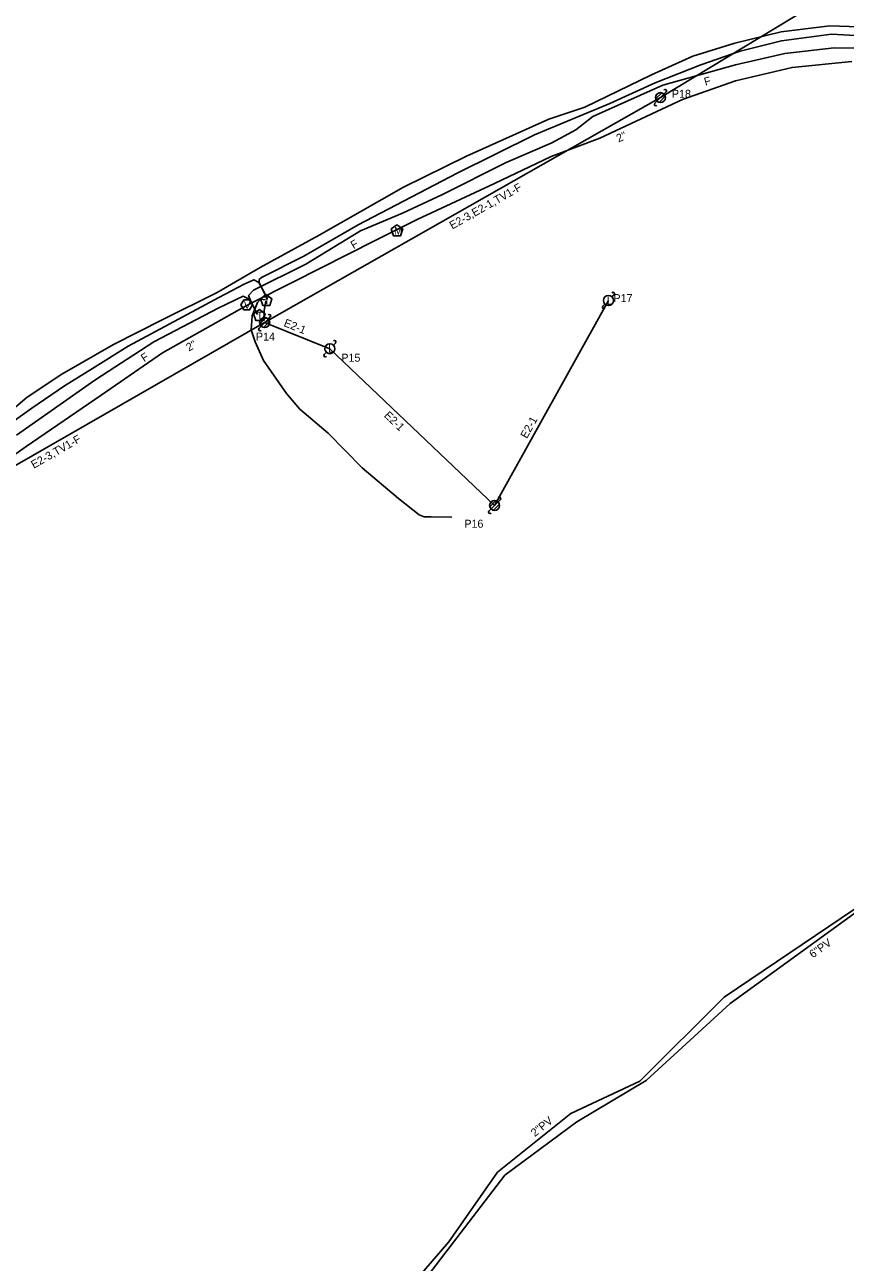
# Model space of a CAD drawing. Extents: x 1741604 to 1825760, y 1164229 to 1194908.
# Drawn here: x 1754935 to 1755344, y 1168344 to 1168963 of the extents above; entities that cross this region are included whole.
import ezdxf

# ---------------------------------------------------------------- set-up
doc = ezdxf.new("R2010")
doc.units = 0
for name, color, linetype in [('RD_EX_SU_H2O', 7, 'Continuous'), ('RD_EX_SU_Ovhd', 7, 'Continuous'), ('RD_EX_SU_Pole', 7, 'Continuous'), ('RD_EX_SU_Sewer', 7, 'Continuous'), ('RD_EX_SU_Telecom', 7, 'Continuous'), ('RD_EX_SU_TX_H2O', 7, 'Continuous'), ('RD_EX_SU_TX_Pole', 7, 'Continuous'), ('RD_EX_SU_TX_Sewer', 7, 'Continuous'), ('RD_EX_SU_TX_Telecom', 7, 'Continuous')]:
    doc.layers.add(name, color=color, linetype=linetype)

msp = doc.modelspace()

# ---------------------------------------------------------------- linework, layer by layer
at = {"layer": 'RD_EX_SU_H2O'}
msp.add_lwpolyline([(1754902.54, 1168728.95), (1754935.35, 1168752.07), (1754972.79, 1168777.79), (1755003.41, 1168799.02), (1755043.45, 1168821.48), (1755047.72, 1168823.74), (1755068.62, 1168834.22), (1755109.76, 1168855.12), (1755130.71, 1168865.51), (1755169.32, 1168883.51), (1755197.53, 1168896.99), (1755221.9, 1168906.29), (1755263.17, 1168925.56), (1755289.7, 1168934.96), (1755317.93, 1168941.55), (1755347.73, 1168944.49)], dxfattribs=at)
for points in [[(1755120.6, 1168862.99), (1755117.7, 1168860.88), (1755118.81, 1168857.47), (1755122.39, 1168857.47), (1755123.5, 1168860.88)], [(1755048.44, 1168822.85), (1755047, 1168825.35), (1755044.11, 1168825.35), (1755042.67, 1168822.85), (1755044.11, 1168820.35), (1755047, 1168820.35)]]:
    msp.add_lwpolyline(points, close=True, dxfattribs=at)
at = {"layer": 'RD_EX_SU_Ovhd'}
for p, q in [((1755252.17, 1168926.49), (1755435.58, 1169037.63)), ((1755054.51, 1168814.05), (1755252.17, 1168926.49)), ((1754862.36, 1168703.77), (1755054.51, 1168814.05))]:
    msp.add_line(p, q, dxfattribs=at)
msp.add_lwpolyline([(1755054.51, 1168814.05), (1755087.08, 1168801.01), (1755169.37, 1168722.69), (1755226.2, 1168825.08)], dxfattribs=at)
at = {"layer": 'RD_EX_SU_Pole'}
for p, q in [((1755249.35, 1168923.66), (1755250.41, 1168924.72)), ((1755249.76, 1168925.84), (1755252.82, 1168928.91)), ((1755250.41, 1168924.72), (1755253.94, 1168928.26)), ((1755251.53, 1168924.08), (1755254.59, 1168927.14)), ((1755253.94, 1168928.26), (1755255, 1168929.32)), ((1755227.97, 1168826.85), (1755229.03, 1168827.91)), ((1755223.38, 1168822.25), (1755224.44, 1168823.31)), ((1755051.69, 1168811.22), (1755052.75, 1168812.28)), ((1755052.1, 1168813.4), (1755055.16, 1168816.46)), ((1755052.75, 1168812.28), (1755056.28, 1168815.81)), ((1755053.87, 1168811.63), (1755056.93, 1168814.69)), ((1755056.28, 1168815.81), (1755057.34, 1168816.88)), ((1755088.85, 1168802.78), (1755089.91, 1168803.84)), ((1755084.26, 1168798.18), (1755085.32, 1168799.24)), ((1755171.14, 1168724.46), (1755172.2, 1168725.52)), ((1755166.55, 1168719.86), (1755167.61, 1168720.92)), ((1755166.96, 1168722.04), (1755170.02, 1168725.11)), ((1755167.61, 1168720.92), (1755171.14, 1168724.46)), ((1755168.73, 1168720.28), (1755171.79, 1168723.34))]:
    msp.add_line(p, q, dxfattribs=at)
for centre in [(1755252.17, 1168926.49), (1755226.2, 1168825.08), (1755054.51, 1168814.05), (1755087.08, 1168801.01), (1755169.37, 1168722.69)]:
    msp.add_circle(centre, 2.5, dxfattribs=at)
for centre, start, end in [((1755254.47, 1168929.85), 315, 135), ((1755249.88, 1168923.13), 135, 315), ((1755228.5, 1168828.44), 315, 135), ((1755223.91, 1168821.72), 135, 315), ((1755056.81, 1168817.41), 315, 135), ((1755052.22, 1168810.69), 135, 315), ((1755089.38, 1168804.37), 315, 135), ((1755084.79, 1168797.65), 135, 315), ((1755171.67, 1168726.05), 315, 135), ((1755167.08, 1168719.33), 135, 315)]:
    msp.add_arc(centre, 0.75, start, end, dxfattribs=at)
at = {"layer": 'RD_EX_SU_Sewer'}
msp.add_line((1755066.51, 1168246.96), (1755174.41, 1168387.89), dxfattribs=at)
for points in [[(1755174.41, 1168387.89), (1755210.34, 1168414.64), (1755245.09, 1168435.23), (1755286.99, 1168473.67), (1755350.64, 1168519.87), (1755404.72, 1168571.84)], [(1755078.96, 1168276.18), (1755146.45, 1168354.69), (1755170.79, 1168389.41), (1755207.43, 1168418.83), (1755241.86, 1168434.85), (1755283.97, 1168476.99), (1755349.04, 1168520.82)]]:
    msp.add_lwpolyline(points, dxfattribs=at)
at = {"layer": 'RD_EX_SU_Telecom'}
for points in [[(1754920.83, 1168764.1), (1754935.86, 1168776.74), (1754953.18, 1168788.35), (1754979.02, 1168803.02), (1755003.65, 1168815.57), (1755030.79, 1168829.13), (1755052.19, 1168841.56), (1755081.74, 1168857.82), (1755123.86, 1168881.69), (1755155.39, 1168897.18), (1755196.48, 1168915.76), (1755214.39, 1168921.76), (1755247.63, 1168937.83), (1755268.41, 1168947.14), (1755289.41, 1168953.77), (1755312.39, 1168959.32), (1755336.84, 1168962.31), (1755360.73, 1168961.58)], [(1755055.71, 1168825.86), (1755051.82, 1168834.05), (1755051.84, 1168835.51), (1755052.96, 1168836.59), (1755074.11, 1168847.21), (1755101.16, 1168862.98), (1755150.62, 1168888.75), (1755189.3, 1168907.97), (1755226.84, 1168923.57), (1755249.6, 1168933.81), (1755272.39, 1168942.94), (1755291.95, 1168949.71), (1755312.56, 1168954.88), (1755337.65, 1168958.12), (1755361.46, 1168956.8)], [(1755050.85, 1168818.07), (1755047.44, 1168825.17), (1755046.49, 1168827.54), (1755048.89, 1168830.31), (1755075.12, 1168843.26), (1755102.41, 1168859.85), (1755123.31, 1168868.66), (1755143.25, 1168878.1), (1755175.07, 1168893.98), (1755197.88, 1168903.97), (1755209.92, 1168910.38), (1755218.42, 1168917.12), (1755253.36, 1168932.67), (1755289.59, 1168942.81), (1755314.38, 1168948.53), (1755338.86, 1168951.41), (1755362.56, 1168951.04)], [(1754923.58, 1168760.84), (1754938.29, 1168771.31), (1754954.55, 1168782.5), (1754968.53, 1168791.05), (1754986.26, 1168802.23), (1755004.67, 1168812.13), (1755031.56, 1168826.61), (1755044.23, 1168833.33), (1755049.07, 1168835.44), (1755051.59, 1168834.04), (1755054.42, 1168828.91), (1755055.82, 1168825.55)], [(1754930.49, 1168757.72), (1754969.72, 1168785.32), (1754999.15, 1168804.5), (1755031.27, 1168821.31), (1755043.74, 1168827.21), (1755047.04, 1168825.55), (1755050.83, 1168818.32)], [(1755054.89, 1168825.5), (1755052.38, 1168825.74), (1755050.97, 1168824.03), (1755048.28, 1168817.45), (1755047.71, 1168810.49), (1755049.7, 1168804.51), (1755053.91, 1168795.05), (1755065.34, 1168778.61), (1755072.07, 1168770.82), (1755086.27, 1168758.74), (1755103.26, 1168741.52), (1755121.43, 1168726.21), (1755131.73, 1168718.05), (1755134.09, 1168716.99), (1755137.65, 1168716.95), (1755147.92, 1168716.87)], [(1755055.14, 1168824.7), (1755054.34, 1168820.07), (1755054.16, 1168814.89)]]:
    msp.add_lwpolyline(points, dxfattribs=at)
for points in [[(1755055.31, 1168828.05), (1755052.45, 1168825.98), (1755053.54, 1168822.63), (1755057.07, 1168822.63), (1755058.16, 1168825.98)], [(1755051.86, 1168820.57), (1755049.01, 1168818.5), (1755050.1, 1168815.14), (1755053.63, 1168815.14), (1755054.72, 1168818.5)]]:
    msp.add_lwpolyline(points, close=True, dxfattribs=at)

# ---------------------------------------------------------------- texts
at = {"layer": 'RD_EX_SU_H2O'}
for s, p in [('M', (1755119.17, 1168858.07)), ('V', (1755044.12, 1168820.98))]:
    msp.add_text(s, height=3.75, dxfattribs=at).set_placement(p)
at = {"layer": 'RD_EX_SU_Ovhd'}
for s, rotation, p in [('E2-3,E2-1,TV1-F', 29.63439, (1755148.22, 1168860.53)), ('E2-1', 338.18865, (1755063.7, 1168812.4)), ('E2-1', 316.41497, (1755113.85, 1168767.26)), ('E2-1', 60.96803, (1755185.47, 1168755.81)), ('E2-3,TV1-F', 29.85119, (1754939.21, 1168740.96))]:
    msp.add_text(s, height=4, rotation=rotation, dxfattribs=at).set_placement(p)
at = {"layer": 'RD_EX_SU_Pole'}
for p in [(1755225.34, 1168823.08), (1755086.22, 1168799.01)]:
    msp.add_text('L', height=4, dxfattribs=at).set_placement(p)
at = {"layer": 'RD_EX_SU_Telecom'}
for p in [(1755054.05, 1168823.18), (1755050.61, 1168815.7)]:
    msp.add_text('T', height=3.75, dxfattribs=at).set_placement(p)
at = {"layer": 'RD_EX_SU_TX_H2O'}
for rotation, p in [(25.02922, (1755231.29, 1168904.05)), (29.29634, (1755016.64, 1168799.56))]:
    msp.add_text('2"', height=4, rotation=rotation, dxfattribs=at).set_placement(p)
at = {"layer": 'RD_EX_SU_TX_Pole'}
for s, p in [('P18', (1755257.9, 1168926.4)), ('P17', (1755228.7, 1168824.26)), ('P14', (1755050.15, 1168805.06)), ('P15', (1755092.8, 1168794.5)), ('P16', (1755154.25, 1168711.53))]:
    msp.add_text(s, height=4, dxfattribs=at).set_placement(p)
at = {"layer": 'RD_EX_SU_TX_Sewer'}
for s, rotation, p in [('6"PV', 35.97266, (1755328.31, 1168496.25)), ('2"PV', 38.75601, (1755189.43, 1168406.95))]:
    msp.add_text(s, height=4, rotation=rotation, dxfattribs=at).set_placement(p)
at = {"layer": 'RD_EX_SU_TX_Telecom'}
for rotation, p in [(15.62934, (1755274.61, 1168932.38)), (31.29954, (1755098.92, 1168850.71)), (33.09442, (1754994.31, 1168794.19))]:
    msp.add_text('F', height=4, rotation=rotation, dxfattribs=at).set_placement(p)

doc.saveas('drawing.dxf')
